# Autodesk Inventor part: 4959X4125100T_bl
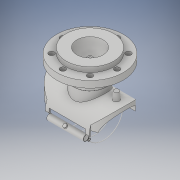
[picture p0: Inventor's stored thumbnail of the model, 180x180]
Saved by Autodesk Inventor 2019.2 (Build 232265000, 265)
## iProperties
Created: 2020-06
Part Number: 4959X4125100T_bl
Material: Generic
Description: Plasson Flanged Branch Saddle 125x100
Document SubType Name: Modeling
Designer: KIM
Density: 1 g/cm^3
Appearance: Default
Author: KIM
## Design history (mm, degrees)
derived "4959X4.ipt"
feature "Solid1::4959X4.ipt" dims "ScaleForDerivedMember" = 10
feature "Solid2::4959X4.ipt" dims "ScaleForDerivedMember" = 10
tag "TaggingFeature1"
body "Solid1"
body "Solid2"
other parameters: "d" = 125 [user parameter], "d_h" = 158 [user parameter], "L" = 242 [user parameter], "LS" = 105 [user parameter], "H1" = 118 [user parameter], "Dt" = 16 [user parameter], "di" = 87 [user parameter], "s_" = 18 [user parameter], "t" = 22 [user parameter], "d72" = 13 [user parameter], "d0" = 242 [user parameter], "d2" = 125 [user parameter], "d4" = 118 [user parameter], "d7" = 87 [user parameter], "d10" = 0.5 [user parameter], "d11" = 1 [user parameter], "d12" = 29.5 [user parameter], "d13" = 16 [user parameter], "d14" = 8 [user parameter], "d16" = 10 deg [user parameter], "d17" = 10 deg [user parameter], "d19" = 0 [user parameter], "d23" = 0 [user parameter], "d26" = 0 [user parameter], "d27" = 145.2 [user parameter], "d28" = 0 [user parameter], "d29" = 121 [user parameter], "d30" = 0 [user parameter], "d31" = 1 [user parameter], "d32" = 1 [user parameter], "d33" = 19.2 [user parameter], "d34" = 9.6 [user parameter], "d35" = 45 deg [user parameter], "d36" = 121 [user parameter], "d37" = 0 [user parameter], "d38" = 5 [user parameter], "d39" = 85 deg [user parameter], "d40" = 29.5 [user parameter], "d41" = 16 [user parameter], "d42" = 88 [user parameter], "d49" = 3 [user parameter], "d50" = 6 [user parameter], "d51" = 5 [user parameter], "d54" = 0 [user parameter], "d57" = 35 deg [user parameter], "d60" = 15.125 [user parameter], "d61" = 1 [user parameter], "d62" = 90 deg [user parameter], "d63" = 2 [user parameter], "d64" = 0 [user parameter], "d65" = 0 [user parameter], "d68" = 30.25 [user parameter], "d70" = 0.57711 [user parameter], "d71" = 10 deg [user parameter], "d73" = 4.55 [user parameter], "d75" = 22 [user parameter], "d77" = 89.25 [user parameter], "d78" = 105 [user parameter], "d79" = 158 [user parameter], "d80" = 1 [user parameter], "d81" = 104.4 [user parameter], "d82" = 121.8 [user parameter], "d83" = 1 [user parameter], "d84" = 16.5 [user parameter], "d87" = 18 [user parameter], "d95" = 360 deg [user parameter]
